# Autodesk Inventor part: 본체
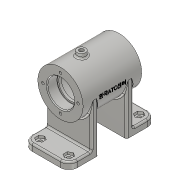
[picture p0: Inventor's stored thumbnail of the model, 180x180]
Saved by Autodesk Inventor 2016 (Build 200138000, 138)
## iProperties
Created: 2017-02
Part Number: 본체
Material: 알루미늄 6061
Document SubType Name: Modeling
Designer: H
Density: 2.7 g/cm^3
Appearance: 알루미늄 - 평지
Mass: 369.098 g
Surface Area: 418.542 cm^2
Volume: 136.703 cm^3
Author: H
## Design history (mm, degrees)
sketch "스케치1"
  geometry: L1 (-52, 27)-(52, 27); L2 (52, 27)-(52, -27); L3 (52, -27)-(-52, -27); L4 (-52, -27)-(-52, 27); L5 (-52, 27)-(52, -27); L6 (52, 27)-(-52, -27); 1 further point
  constraints: 12 end point, 2 midpoint, 2 parallel, 1 horizontal, 1 perpendicular
  dimensions: "d0" = 104 distance of L2.end L3.end; "d1" = 54 distance of L1.end L2.end
extrude "돌출1" new body sketch "스케치1" distance "d2" = 8; taper "d3" = 0 deg
sketch "스케치2"
  geometry: L1 (0, 0)-(0, 8) reference; L2 (0, 8)-(104, 8) reference; L3 (104, 8)-(104, 0) reference; L4 (104, 0)-(0, 0) reference; L5 (35, 0)-(69, 0); L6 (69, 0)-(69, 8); L7 (69, 8)-(35, 8); L8 (35, 8)-(35, 0); 2 further points
  constraints: 8 end point, 2 midpoint, 2 parallel, 2 point on line, 1 horizontal, 1 perpendicular
  dimensions: "d4" = 17 distance from line of L8 point (52, 0)
extrude "돌출2" cut sketch "스케치2" stored distance "d5" = 8; taper "d6" = 0 deg
sketch "스케치3"
  geometry: L1 (-17, 8)-(-17, 0) reference; L2 (-17, 0)-(-52, 0) reference; L3 (-52, 0)-(-52, 8) reference; L4 (-52, 8)-(-17, 8) reference; L5 (52, 0)-(17, 0) reference; L6 (17, 0)-(17, 8) reference; L7 (17, 8)-(52, 8) reference; L8 (52, 8)-(52, 0) reference; L9 (-35, 60)-(35, 60); L10 (-35, 60)-(35, 60); L11 (35, 60)-(35, 87); L12 (35, 87)-(-35, 87); L13 (-35, 87)-(-35, 60); L14 (-17, 8)-(-25, 8); L15 (-25, 8)-(-25, 60); L16 (-25, 60)-(-17, 60); L17 (-17, 60)-(-17, 8); L18 (17, 8)-(25, 8); L19 (25, 8)-(25, 60); L20 (25, 60)-(17, 60); L21 (17, 60)-(17, 8); L22 (-10, 80.673)-(-5, 80.673); L23 (-5, 80.673)-(-5, 92); L24 (-5, 92)-(-10, 92); L25 (-10, 92)-(-10, 80.673); 2 further points
  constraints: 34 end point, 8 parallel, 5 horizontal, 4 perpendicular, 2 collinear, 1 midpoint, 1 vertical alignment
  dimensions: "d7" = 60 distance between parallel lines of L2 L9; "d8" = 70 distance of L9.start L9.end; "d9" = 54 diameter of L12 L9; "d10" = 8 distance of L15.end L16.end; "d11" = 8 distance of L20.end L19.end; "d12" = 25 distance between parallel lines of L13 L25; "d13" = 5 distance between parallel lines of L12 L24; "d14" = 10 diameter of L23 L25; "d15" = 11.32659 distance of L22.end L23.end
  node "절단 모서리 투영2"
revolve "회전1" stored, may be unused: angle "d16" = 90 deg
extrude "돌출3" join sketch "스케치3" stored distance "d17" = 54; taper "d18" = 0 deg
revolve "회전2" stored, may be unused: angle "d19" = 90 deg
fillet "모깎기1" dims "d20" = 10
node "작업 평면1"
sketch "스케치4"
  geometry: L1 (-18, 87)-(52, 87) reference; L2 (-18, 33)-(-18, 87) reference; 2 further points
  constraints: 1 other
  dimensions: "d22" = 27 distance from line of L1 point (17, 60); "d23" = 35 distance from line of point (17, 60) L2
feature "엠보싱1" sketch "스케치4" dims "d0" = 104, "d1" = 54, "d24" = 0.5, "d25" = 0
sketch "스케치5"
  geometry: L1 (61.941, 27.431)-(61.906, 26.933) reference; L2 (61.576, 26.954)-(61.605, 27.453) reference; L3 (60, 0)-(33, 0); L4 (60, 0)-(34.84, -16.339); L5 (34.84, -16.339)-(38.108, -21.371); L6 (38.108, -21.371)-(63.268, -5.032); L7 (63.268, -5.032)-(60, 0); A1 r 27.5 centre (60, 0) between (61.941, 27.431) and (61.605, 27.453) reference; A2 r 27 centre (60, 0) between (61.576, 26.954) and (61.906, 26.933) reference; 1 further point
  constraints: 10 end point, 2 parallel, 1 horizontal, 1 perpendicular, 1 point on circle
  dimensions: "d26" = 30 distance of L5.end L6.end; "d27" = 33 deg angle of L3 L4; "d28" = 12 diameter of L6 L4
revolve "회전3" sketch "스케치5" stored, may be unused: angle "d29" = 90 deg
sketch "스케치6"
  geometry: L1 (-35, 33)-(-35, 87) reference; L2 (35, 33)-(35, 87) reference; L3 (-35, 60)-(35, 60); L4 (-42, 0)-(-17, 0) reference; L5 (-35, 60)-(-23, 60); L6 (-23, 60)-(-23, 76); L7 (-23, 76)-(-35, 76); L8 (-35, 76)-(-35, 60); L9 (-23, 60)-(-20, 60); L10 (-20, 60)-(-20, 74); L11 (-20, 74)-(-23, 74); L12 (-23, 74)-(-23, 60); L13 (-20, 60)-(20, 60); L14 (20, 60)-(20, 82); L15 (20, 82)-(-20, 82); L16 (-20, 82)-(-20, 60); L17 (20, 60)-(23, 60); L18 (23, 60)-(23, 74); L19 (23, 74)-(20, 74); L20 (20, 74)-(20, 60); L21 (23, 60)-(35, 60); L22 (35, 60)-(35, 76); L23 (35, 76)-(23, 76); L24 (23, 76)-(23, 60); 2 further points
  constraints: 42 end point, 10 parallel, 6 horizontal, 5 perpendicular, 1 midpoint, 1 point on line, 1 vertical alignment
  dimensions: "d30" = 70 distance of L3.start L3.end; "d31" = 60 distance between parallel lines of L4 L3; "d32" = 32 diameter of L7 L3; "d33" = 28 diameter of L11 L3; "d34" = 44 diameter of L15 L3; "d35" = 28 diameter of L19 L3; "d36" = 32 diameter of L23 L3; "d37" = 12 distance of L6.end L7.end; "d38" = 3 distance between parallel lines of L10 L12; "d39" = 40 distance of L14.end L15.end; "d40" = 3 distance of L18.end L19.end
revolve "회전4" sketch "스케치6" stored, may be unused: angle "d41" = 90 deg
sketch "스케치7"
  geometry: C1 r 5 at (0, 0) reference; 1 further point
hole "구멍1" sketch "스케치7" at (0, 0) diameter "d42" = 5.188; stored, may be unused: countersink angle "d46" = 90 deg, drill point angle "d48" = 118 deg; dims "d43" = 12, "d44" = 4, "d45" = 2, "d47" = 20
sketch "스케치8"
  geometry: C1 r 6 at (0, 0) reference; 1 further point
hole "구멍2" sketch "스케치8" at (0, 0) diameter "d49" = 5.188; stored, may be unused: countersink angle "d53" = 90 deg, drill point angle "d55" = 118 deg; dims "d50" = 12, "d51" = 4, "d52" = 2, "d54" = 20
fillet "모깎기2" dims "d56" = 2
fillet "모깎기3" dims "d57" = 2
fillet "모깎기4" dims "d58" = 2
fillet "모깎기5" dims "d59" = 3
chamfer "모따기1" distance "d60" = 1; stored, may be unused: second distance "d61" = 2, angle "d62" = 45 deg
sketch "스케치9" dims "d63" = 42
  geometry: C1 r 27 at (0, 0) reference; C2 r 17 at (0, 0) reference; 3 further points
  constraints: 2 vertical alignment, 1 coincident, 2 other
hole "구멍3" sketch "스케치9" at (0, 21) diameter "d64" = 3.242; stored, may be unused: countersink angle "d68" = 90 deg, drill point angle "d70" = 118 deg; dims "d65" = 8, "d66" = 4, "d67" = 2, "d69" = 10
node "작업 평면2"
sketch "스케치10" dims "d74" = 9, "d75" = 9, "d76" = 9, "d77" = 9
  geometry: L1 (-19, -27)-(-23.536, -27) reference; L2 (-42, -25)-(-27, -25) reference; L3 (-50, 17)-(-50, -17) reference; L4 (-27, 25)-(-42, 25) reference; L5 (-27, 25)-(-27, -25) reference; L6 (-17, 25)-(-17, -25) reference; L7 (-23.536, 27)-(-19, 27) reference; L8 (42, 25)-(27, 25) reference; L9 (50, -17)-(50, 17) reference; L10 (27, -25)-(42, -25) reference; L11 (27, -25)-(27, 25) reference; L12 (19, 27)-(23.536, 27) reference; L13 (17, -25)-(17, 25) reference; L14 (23.536, -27)-(19, -27) reference; L15 (-39.402, -12.5)-(-36.804, -17); L16 (-36.804, -17)-(-39.402, -21.5); L17 (-39.402, -21.5)-(-44.598, -21.5); L18 (-44.598, -21.5)-(-47.196, -17); L19 (-47.196, -17)-(-44.598, -12.5); L20 (-44.598, -12.5)-(-39.402, -12.5); L21 (-42, -17)-(-42, -12.5); L22 (-36.804, 17)-(-39.402, 12.5); L23 (-39.402, 12.5)-(-44.598, 12.5); L24 (-42, 17)-(-42, 21.5); L25 (-44.598, 21.5)-(-39.402, 21.5); L26 (-44.598, 12.5)-(-47.196, 17); L27 (-47.196, 17)-(-44.598, 21.5); L28 (-39.402, 21.5)-(-36.804, 17); L29 (47.196, 17)-(44.598, 12.5); L30 (44.598, 12.5)-(39.402, 12.5); L31 (42, 17)-(42, 21.5); L32 (39.402, 21.5)-(44.598, 21.5); L33 (39.402, 12.5)-(36.804, 17); L34 (36.804, 17)-(39.402, 21.5); L35 (44.598, 21.5)-(47.196, 17); L36 (47.196, -17)-(44.598, -21.5); L37 (44.598, -21.5)-(39.402, -21.5); L38 (42, -17)-(42, -12.5); L39 (39.402, -12.5)-(44.598, -12.5); L40 (39.402, -21.5)-(36.804, -17); L41 (36.804, -17)-(39.402, -12.5); L42 (44.598, -12.5)-(47.196, -17); A1 r 2 centre (-19, -25) between (-19, -27) and (-17, -25) reference; A2 r 8 centre (-42, -17) between (-50, -17) and (-42, -25) reference; A3 r 8 centre (-42, 17) between (-42, 25) and (-50, 17) reference; A4 r 2 centre (-19, 25) between (-17, 25) and (-19, 27) reference; A5 r 8 centre (42, 17) between (50, 17) and (42, 25) reference; A6 r 8 centre (42, -17) between (42, -25) and (50, -17) reference; A7 r 2 centre (19, 25) between (19, 27) and (17, 25) reference; A8 r 2 centre (19, -25) between (17, -25) and (19, -27) reference; 5 further points
  constraints: 56 end point, 5 coincident, 4 midpoint, 4 vertical, 4 vertical alignment, 64 other
extrude "돌출4" cut sketch "스케치10" distance "d78" = 3; taper "d79" = 0 deg
sketch "스케치11"
  geometry: L1 (44.598, 21.5)-(39.402, 21.5) reference; L2 (39.402, 21.5)-(36.804, 17) reference; L3 (36.804, 17)-(39.402, 12.5) reference; L4 (39.402, 12.5)-(44.598, 12.5) reference; L5 (44.598, 12.5)-(47.196, 17) reference; L6 (47.196, 17)-(44.598, 21.5) reference; L7 (-39.402, -12.5)-(-44.598, -12.5) reference; L8 (-44.598, -12.5)-(-47.196, -17) reference; L9 (-47.196, -17)-(-44.598, -21.5) reference; L10 (-44.598, -21.5)-(-39.402, -21.5) reference; L11 (-39.402, -21.5)-(-36.804, -17) reference; L12 (-36.804, -17)-(-39.402, -12.5) reference; L13 (-39.402, 21.5)-(-44.598, 21.5) reference; L14 (-44.598, 21.5)-(-47.196, 17) reference; L15 (-47.196, 17)-(-44.598, 12.5) reference; L16 (-44.598, 12.5)-(-39.402, 12.5) reference; L17 (-39.402, 12.5)-(-36.804, 17) reference; L18 (-36.804, 17)-(-39.402, 21.5) reference; L19 (44.598, -12.5)-(39.402, -12.5) reference; L20 (39.402, -12.5)-(36.804, -17) reference; L21 (36.804, -17)-(39.402, -21.5) reference; L22 (39.402, -21.5)-(44.598, -21.5) reference; L23 (44.598, -21.5)-(47.196, -17) reference; L24 (47.196, -17)-(44.598, -12.5) reference; L25 (52, 17)-(52, -17) reference; L26 (42, -27)-(19, -27) reference; L27 (17, -25)-(17, 25) reference; L28 (19, 27)-(42, 27) reference; L29 (-42, 27)-(-19, 27) reference; L30 (-17, 25)-(-17, -25) reference; L31 (-19, -27)-(-42, -27) reference; L32 (-52, -17)-(-52, 17) reference; C1 r 2.5 at (-42, -17); C2 r 2.5 at (-42, 17); C3 r 2.5 at (42, 17); C4 r 2.5 at (42, -17); A1 r 10 centre (42, 17) between (52, 17) and (42, 27) reference; A2 r 10 centre (42, -17) between (42, -27) and (52, -17) reference; A3 r 2 centre (19, -25) between (17, -25) and (19, -27) reference; A4 r 2 centre (19, 25) between (19, 27) and (17, 25) reference; A5 r 10 centre (-42, 17) between (-42, 27) and (-52, 17) reference; A6 r 2 centre (-19, 25) between (-17, 25) and (-19, 27) reference; A7 r 2 centre (-19, -25) between (-19, -27) and (-17, -25) reference; A8 r 10 centre (-42, -17) between (-52, -17) and (-42, -27) reference; 1 further point
  constraints: 4 centre point, 1 coincident
  dimensions: "d80" = 5 diameter of C1; "d81" = 5 diameter of C2; "d82" = 5 diameter of C3; "d83" = 5 diameter of C4
extrude "돌출5" cut sketch "스케치11" distance "d84" = 5; taper "d85" = 0 deg
fillet "모깎기6" dims "d86" = 2
fillet "모깎기7" dims "d87" = 0.3
node "솔리드1"
pattern_circular "원형 패턴1" dims angle "d72" = 360 deg
mirror "대칭1"
node "투영된 루프1"
node "투영된 루프2"
node "투영된 루프3"
node "절단 모서리 투영1"
node "절단 모서리 투영3"
node "절단 모서리 투영4"
node "절단 모서리 투영5"
other parameters: "d21" = 25
